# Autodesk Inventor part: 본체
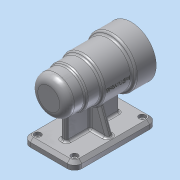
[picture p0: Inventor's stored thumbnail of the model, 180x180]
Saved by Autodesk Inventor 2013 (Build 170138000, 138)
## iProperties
Created: 2016-06
Part Number: 본체
Material: 알루미늄 6061
Document SubType Name: Modeling
Designer: dgall
Density: 2.71 g/cm^3
Mass: 673.897 g
Surface Area: 647.222 cm^2
Volume: 248.67 cm^3
Author: dgall
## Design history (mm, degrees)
sketch "스케치1"
  geometry: L1 (-56, 0)-(56, 0); L2 (-56, 0)-(-56, 25); L3 (-56, 25)-(-31, 25); L4 (-31, 25)-(-31, 27); L5 (-31, 27)-(-11, 27); L6 (-11, 27)-(-11, 30); L7 (-11, 30)-(28, 30); L8 (28, 30)-(28, 34); L9 (28, 34)-(56, 34); L10 (56, 34)-(56, 0); 2 further points
  constraints: 20 end point, 6 parallel, 2 perpendicular, 1 coincident, 1 horizontal, 1 midpoint, 1 vertical
  dimensions: "d0" = 112 distance of L1.start L1.end; "d2" = 25 distance between parallel lines of L4 L2; "d3" = 45 distance between parallel lines of L6 L2; "d4" = 84 distance between parallel lines of L8 L2; "d5" = 50 diameter of L3 L1; "d6" = 54 diameter of L5 L1; "d7" = 60 diameter of L7 L1; "d8" = 68 diameter of L9 L1
revolve "회전1" sketch "스케치1" stored, may be unused: angle "d9" = 90 deg
sketch "스케치2"
  geometry: L1 (-50, 0)-(56, 0); L2 (56, -34)-(56, 34) reference; L3 (56, 21)-(41, 21); L4 (41, 21)-(41, 24); L5 (41, 24)-(-13, 24); L6 (-13, 24)-(-13, 21); L7 (-13, 21)-(-25, 21); L8 (-25, 21)-(-25, 17.5); L9 (-25, 17.5)-(-43, 17.5); L10 (-43, 17.5)-(-43, 16); L11 (-43, 16)-(-47, 16); L12 (-47, 16)-(-47, 10.5); L13 (-47, 10.5)-(-50, 10.5); L14 (-50, 10.5)-(-50, 0); 1 further point
  constraints: 26 end point, 9 parallel, 2 perpendicular, 2 point on line, 1 collinear, 1 horizontal, 1 midpoint
  dimensions: "d10" = 21 diameter of L13 L1; "d12" = 32 diameter of L11 L1; "d13" = 35 diameter of L9 L1; "d14" = 42 diameter of L7 L1; "d15" = 48 diameter of L5 L1; "d16" = 42 diameter of L3 L1; "d17" = 3 distance between parallel lines of L12 L14; "d19" = 18 distance between parallel lines of L8 L10; "d20" = 12 distance between parallel lines of L6 L8; "d21" = 54 distance between parallel lines of L4 L6; "d22" = 15 distance between parallel lines of L2 L4; "d92" = 4 distance between parallel lines of L10 L12
revolve "회전2" sketch "스케치2" stored, may be unused: angle "d23" = 90 deg
node "작업 평면1"
sketch "스케치3"
  geometry: L1 (34, 56)-(-34, 56) reference; L2 (-35, 56)-(-35, -56); L3 (-35, -56)-(35, -56); L4 (35, -56)-(35, 56); L5 (-35, 56)-(35, 56); 2 further points
  constraints: 8 end point, 3 perpendicular, 2 point on line, 1 collinear, 1 midpoint, 1 vertical alignment
  dimensions: "d25" = 70 distance of L2.start L4.end; "d27" = 112 distance of L2.start L2.end
extrude "돌출1" join sketch "스케치3" distance "d28" = 10; taper "d29" = 0 deg
sketch "스케치4"
  geometry: L1 (-4, -36)-(-4, 36); L2 (4, 36)-(4, -36); L3 (-4, 36)-(4, 36); L4 (-4, -36)-(4, -36); L5 (-35, 56)-(35, 56) reference; 4 further points
  constraints: 8 end point, 3 midpoint, 2 parallel, 2 vertical alignment, 1 horizontal alignment, 1 perpendicular, 1 vertical
  dimensions: "d30" = 8 distance between parallel lines of L2 L1; "d32" = 20 distance between parallel lines of L5 L3
extrude "돌출2" join sketch "스케치4" stored distance "d33" = 10; taper "d34" = 0 deg
node "작업 평면2"
sketch "스케치5"
  geometry: L1 (70, 0)-(0, 0) reference; L2 (7, 0)-(16.995, 27.462); L3 (0, 0)-(0, -10) reference; 1 further point
  constraints: 2 end point, 1 point on line
  dimensions: "d35" = 7 distance from line of L3 L2.start; "d36" = 110 deg angle of L1 L2
feature "리브1" sketch "스케치5" dims "d37" = 1, "d38" = 8, "d39" = 0, "d40" = 0, "d41" = 1, "d42" = 1
sketch "스케치6"
  geometry: L1 (0, 0)-(0, 26); C1 r 34 at (0, 0) reference; 1 further point
  constraints: 2 end point, 1 coincident, 1 vertical
  dimensions: "d43" = 26 distance of L1.start L1.end
hole "구멍1" sketch "스케치6" at (0, 26) diameter "d44" = 3.242; stored, may be unused: countersink angle "d48" = 90 deg, drill point angle "d50" = 118 deg; dims "d45" = 8, "d46" = 4, "d47" = 2, "d49" = 11
node "작업 평면3"
sketch "스케치7"
  geometry: L1 (47.5, -34)-(47.5, 34) reference; 2 further points
  constraints: 1 horizontal alignment, 1 other
  dimensions: "d54" = 48 distance from line of L1 point (-0.5, 0)
feature "엠보싱1" sketch "스케치7" dims "d0" = 112, "d2" = 25, "d3" = 45, "d4" = 84, "d5" = 50, "d6" = 54, "d7" = 60, "d8" = 68, "d10" = 21, "d12" = 32, "d13" = 35, "d14" = 42, "d15" = 48, "d16" = 42, "d17" = 3, "d19" = 18, "d20" = 12, "d21" = 54, "d22" = 15, "d55" = 0.5, "d56" = 0, "d92" = 4
fillet "모깎기5" dims "d87" = 3, "d88" = 0.3
chamfer "모따기2" distance "d89" = 1; stored, may be unused: second distance "d90" = 2, angle "d91" = 45 deg
fillet "모깎기6" dims "d93" = 10
fillet "모깎기7" dims "d94" = 3
fillet "모깎기8" dims "d95" = 3
fillet "모깎기9" dims "d96" = 3
chamfer "모따기3" distance "d97" = 4; stored, may be unused: second distance "d98" = 2, angle "d99" = 45 deg
hole "구멍4" diameter "d102" = 5; stored, may be unused: countersink angle "d106" = 90 deg, drill point angle "d108" = 118 deg; dims "d100" = 10, "d101" = 10, "d103" = 6, "d104" = 9, "d105" = 4, "d107" = 8
hole "구멍5" diameter "d111" = 5; stored, may be unused: countersink angle "d115" = 90 deg, drill point angle "d117" = 118 deg; dims "d109" = 10, "d110" = 10, "d112" = 6, "d113" = 9, "d114" = 4, "d116" = 8
node "솔리드1"
mirror "대칭1"
pattern_circular "원형 패턴1" dims angle "d52" = 360 deg
mirror "대칭3"
